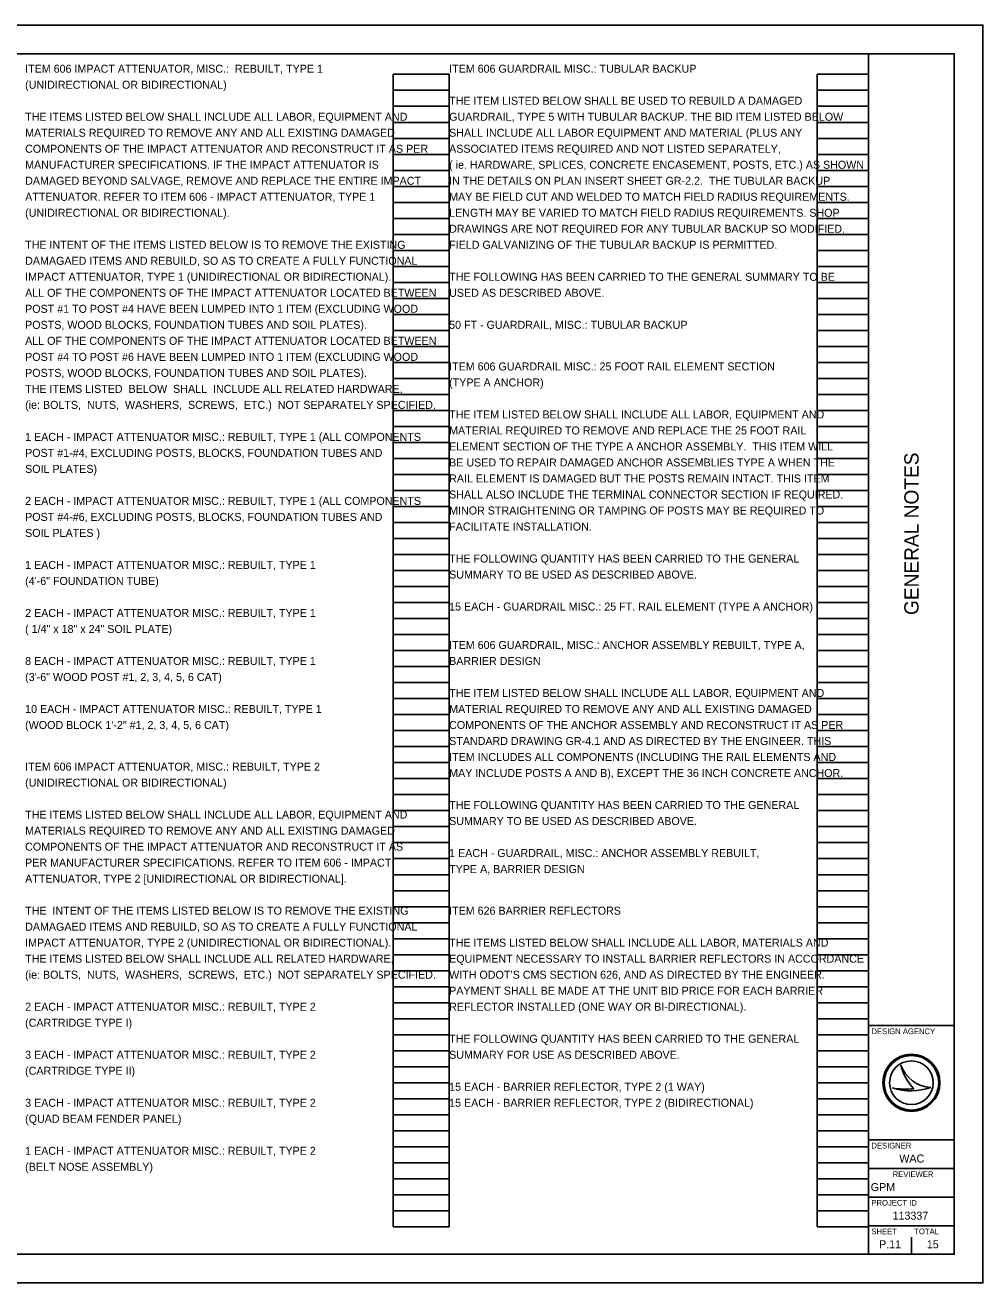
# Model space of a CAD drawing. Extents: x 0 to 34, y 0 to 22.
# Drawn here: x 17.24 to 34, y 0 to 22 of the extents above; entities that cross this region are included whole.
import ezdxf

# ---------------------------------------------------------------- set-up
doc = ezdxf.new("R2010")
doc.units = 0
for name, color, linetype in [('SH_Border', 7, 'Continuous'), ('SH_Cut_Line', 7, 'Continuous'), ('SH_Data', 7, 'Continuous'), ('SH_Text', 7, 'Continuous')]:
    doc.layers.add(name, color=color, linetype=linetype)

msp = doc.modelspace()

# ---------------------------------------------------------------- linework, layer by layer
at = {"layer": 'SH_Border'}
for p, q in [((32, 0.5), (32, 21.5)), ((32, 4.5), (33.5, 4.5)), ((32, 2.5), (33.5, 2.5)), ((32, 2), (33.5, 2)), ((32, 1.5), (33.5, 1.5)), ((32, 1), (33.5, 1))]:
    msp.add_line(p, q, dxfattribs=at)
msp.add_lwpolyline([(1.5, 21.5), (33.5, 21.5), (33.5, 0.5), (1.5, 0.5)], close=True, dxfattribs=at)
at = {"layer": 'SH_Cut_Line'}
msp.add_lwpolyline([(0, 0), (34, 0), (34, 22), (0, 22)], close=True, dxfattribs=at)
at = {"layer": 'SH_Data'}
for p, q in [((23.68, 0.98), (23.68, 21.14)), ((23.68, 21.14), (24.66, 21.14)), ((24.66, 0.98), (24.66, 21.14)), ((31.1, 0.98), (31.1, 21.14)), ((31.1, 21.14), (32, 21.14)), ((32, 0.98), (32, 21.14)), ((23.68, 20.86), (24.66, 20.86)), ((31.1, 20.86), (32, 20.86)), ((23.68, 20.58), (24.66, 20.58)), ((31.1, 20.58), (32, 20.58)), ((23.68, 20.3), (24.66, 20.3)), ((31.1, 20.3), (32, 20.3)), ((23.68, 20.02), (24.66, 20.02)), ((31.1, 20.02), (32, 20.02)), ((23.68, 19.74), (24.66, 19.74)), ((31.1, 19.74), (32, 19.74)), ((23.68, 19.46), (24.66, 19.46)), ((31.1, 19.46), (32, 19.46)), ((23.68, 19.18), (24.66, 19.18)), ((31.1, 19.18), (32, 19.18)), ((23.68, 18.9), (24.66, 18.9)), ((31.1, 18.9), (32, 18.9)), ((23.68, 18.62), (24.66, 18.62)), ((31.1, 18.62), (32, 18.62)), ((23.68, 18.34), (24.66, 18.34)), ((31.1, 18.34), (32, 18.34)), ((23.68, 18.06), (24.66, 18.06)), ((31.1, 18.06), (32, 18.06)), ((23.68, 17.78), (24.66, 17.78)), ((31.1, 17.78), (32, 17.78)), ((23.68, 17.5), (24.66, 17.5)), ((31.1, 17.5), (32, 17.5)), ((23.68, 17.22), (24.66, 17.22)), ((31.1, 17.22), (32, 17.22)), ((23.68, 16.94), (24.66, 16.94)), ((31.1, 16.94), (32, 16.94)), ((23.68, 16.66), (24.66, 16.66)), ((31.1, 16.66), (32, 16.66)), ((23.68, 16.38), (24.66, 16.38)), ((31.1, 16.38), (32, 16.38)), ((23.68, 16.1), (24.66, 16.1)), ((31.1, 16.1), (32, 16.1)), ((23.68, 15.82), (24.66, 15.82)), ((31.1, 15.82), (32, 15.82)), ((23.68, 15.54), (24.66, 15.54)), ((31.1, 15.54), (32, 15.54)), ((23.68, 15.26), (24.66, 15.26)), ((31.1, 15.26), (32, 15.26)), ((23.68, 14.98), (24.66, 14.98)), ((31.1, 14.98), (32, 14.98)), ((23.68, 14.7), (24.66, 14.7)), ((31.1, 14.7), (32, 14.7)), ((23.68, 14.42), (24.66, 14.42)), ((31.1, 14.42), (32, 14.42)), ((23.68, 14.14), (24.66, 14.14)), ((31.1, 14.14), (32, 14.14)), ((23.68, 13.86), (24.66, 13.86)), ((31.1, 13.86), (32, 13.86)), ((23.68, 13.58), (24.66, 13.58)), ((31.1, 13.58), (32, 13.58)), ((23.68, 13.3), (24.66, 13.3)), ((31.1, 13.3), (32, 13.3)), ((23.68, 13.02), (24.66, 13.02)), ((31.1, 13.02), (32, 13.02)), ((23.68, 12.74), (24.66, 12.74)), ((31.1, 12.74), (32, 12.74)), ((23.68, 12.46), (24.66, 12.46)), ((31.1, 12.46), (32, 12.46)), ((23.68, 12.18), (24.66, 12.18)), ((31.1, 12.18), (32, 12.18)), ((23.68, 11.9), (24.66, 11.9)), ((31.1, 11.9), (32, 11.9)), ((23.68, 11.62), (24.66, 11.62)), ((31.1, 11.62), (32, 11.62)), ((23.68, 11.34), (24.66, 11.34)), ((31.1, 11.34), (32, 11.34)), ((23.68, 11.06), (24.66, 11.06)), ((31.1, 11.06), (32, 11.06)), ((23.68, 10.78), (24.66, 10.78)), ((31.1, 10.78), (32, 10.78)), ((23.68, 10.5), (24.66, 10.5)), ((31.1, 10.5), (32, 10.5)), ((23.68, 10.22), (24.66, 10.22)), ((31.1, 10.22), (32, 10.22)), ((23.68, 9.94), (24.66, 9.94)), ((31.1, 9.94), (32, 9.94)), ((23.68, 9.66), (24.66, 9.66)), ((31.1, 9.66), (32, 9.66)), ((23.68, 9.38), (24.66, 9.38)), ((31.1, 9.38), (32, 9.38)), ((23.68, 9.1), (24.66, 9.1)), ((31.1, 9.1), (32, 9.1)), ((23.68, 8.82), (24.66, 8.82)), ((31.1, 8.82), (32, 8.82)), ((23.68, 8.54), (24.66, 8.54)), ((31.1, 8.54), (32, 8.54)), ((23.68, 8.26), (24.66, 8.26)), ((31.1, 8.26), (32, 8.26)), ((23.68, 7.98), (24.66, 7.98)), ((31.1, 7.98), (32, 7.98)), ((23.68, 7.7), (24.66, 7.7)), ((31.1, 7.7), (32, 7.7)), ((23.68, 7.42), (24.66, 7.42)), ((31.1, 7.42), (32, 7.42)), ((23.68, 7.14), (24.66, 7.14)), ((31.1, 7.14), (32, 7.14)), ((23.68, 6.86), (24.66, 6.86)), ((31.1, 6.86), (32, 6.86)), ((23.68, 6.58), (24.66, 6.58)), ((31.1, 6.58), (32, 6.58)), ((23.68, 6.3), (24.66, 6.3)), ((31.1, 6.3), (32, 6.3)), ((23.68, 6.02), (24.66, 6.02)), ((31.1, 6.02), (32, 6.02)), ((23.68, 5.74), (24.66, 5.74)), ((31.1, 5.74), (32, 5.74)), ((23.68, 5.46), (24.66, 5.46)), ((31.1, 5.46), (32, 5.46)), ((23.68, 5.18), (24.66, 5.18)), ((31.1, 5.18), (32, 5.18)), ((23.68, 4.9), (24.66, 4.9)), ((31.1, 4.9), (32, 4.9)), ((23.68, 4.62), (24.66, 4.62)), ((31.1, 4.62), (32, 4.62)), ((23.68, 4.34), (24.66, 4.34)), ((31.1, 4.34), (32, 4.34)), ((23.68, 4.06), (24.66, 4.06)), ((31.1, 4.06), (32, 4.06)), ((23.68, 3.78), (24.66, 3.78)), ((31.1, 3.78), (32, 3.78)), ((32.567, 3.81), (32.567, 3.81)), ((23.68, 3.5), (24.66, 3.5)), ((31.1, 3.5), (32, 3.5)), ((32.417, 3.41), (32.417, 3.41)), ((32.75, 3.5), (32.75, 3.5)), ((33.087, 3.419), (33.087, 3.419)), ((23.68, 3.22), (24.66, 3.22)), ((31.1, 3.22), (32, 3.22)), ((23.68, 2.94), (24.66, 2.94)), ((31.1, 2.94), (32, 2.94)), ((23.68, 2.66), (24.66, 2.66)), ((31.1, 2.66), (32, 2.66)), ((23.68, 2.38), (24.66, 2.38)), ((31.1, 2.38), (32, 2.38)), ((23.68, 2.1), (24.66, 2.1)), ((31.1, 2.1), (32, 2.1)), ((23.68, 1.82), (24.66, 1.82)), ((31.1, 1.82), (32, 1.82)), ((23.68, 1.54), (24.66, 1.54)), ((31.1, 1.54), (32, 1.54)), ((23.68, 1.26), (24.66, 1.26)), ((31.1, 1.26), (32, 1.26)), ((23.68, 0.98), (24.66, 0.98)), ((31.1, 0.98), (32, 0.98)), ((32.375, 0.675), (32.375, 0.675)), ((32.75, 0.5), (32.75, 0.8))]:
    msp.add_line(p, q, dxfattribs=at)
for radius in [0.5, 0.477, 0.477, 0.382]:
    msp.add_circle((32.75, 3.5), radius, dxfattribs=at)
for centre, radius, start, end in [((33.116, 3.998), 0.58, 198.9257, 198.9319), ((33.347, 3.97), 0.796, 191.6379, 191.6421), ((33.116, 3.998), 0.58, 198.9319, 267.1657), ((33.347, 3.97), 0.796, 191.6421, 226.0947), ((32.739, 4.37), 1.013, 251.4576, 290.0832), ((32.648, 4.654), 1.266, 259.4964, 259.4995), ((32.739, 4.37), 1.013, 251.4527, 251.4576), ((32.648, 4.654), 1.266, 259.4995, 276.6672)]:
    msp.add_arc(centre, radius, start, end, dxfattribs=at)

# ---------------------------------------------------------------- texts
msp.add_text('GENERAL NOTES', height=0.25, rotation=90, dxfattribs=at).set_placement((32.875, 11.682))
for s, height, p in [('DESIGN AGENCY', 0.1, (32.05, 4.35)), ('DESIGNER', 0.1, (32.05, 2.35)), ('WAC', 0.14, (32.538, 2.105)), ('REVIEWER', 0.1, (32.422, 1.85)), ('GPM', 0.14, (32.038, 1.605)), ('PROJECT ID', 0.1, (32.05, 1.35)), ('113337', 0.14, (32.42, 1.105)), ('SHEET', 0.1, (32.05, 0.85)), ('TOTAL', 0.1, (32.8, 0.85)), ('P.11', 0.14, (32.184, 0.605)), ('15', 0.14, (33.02, 0.605))]:
    msp.add_text(s, height=height, dxfattribs=at).set_placement(p)
at = {"layer": 'SH_Text'}
for s, p in [('ITEM 606 IMPACT ATTENUATOR, MISC.:  REBUILT, TYPE 1', (17.24, 21.168)), ('ITEM 606 GUARDRAIL MISC.: TUBULAR BACKUP', (24.66, 21.168)), ('(UNIDIRECTIONAL OR BIDIRECTIONAL)', (17.24, 20.888)), ('THE ITEM LISTED BELOW SHALL BE USED TO REBUILD A DAMAGED', (24.66, 20.608)), ('THE ITEMS LISTED BELOW SHALL INCLUDE ALL LABOR, EQUIPMENT AND', (17.24, 20.328)), ('GUARDRAIL, TYPE 5 WITH TUBULAR BACKUP. THE BID ITEM LISTED BELOW', (24.66, 20.328)), ('MATERIALS REQUIRED TO REMOVE ANY AND ALL EXISTING DAMAGED', (17.24, 20.048)), ('SHALL INCLUDE ALL LABOR EQUIPMENT AND MATERIAL (PLUS ANY', (24.66, 20.048)), ('COMPONENTS OF THE IMPACT ATTENUATOR AND RECONSTRUCT IT AS PER', (17.24, 19.768)), ('ASSOCIATED ITEMS REQUIRED AND NOT LISTED SEPARATELY,', (24.66, 19.768)), ('MANUFACTURER SPECIFICATIONS. IF THE IMPACT ATTENUATOR IS', (17.24, 19.488)), ('( ie. HARDWARE, SPLICES, CONCRETE ENCASEMENT, POSTS, ETC.) AS SHOWN', (24.66, 19.488)), ('DAMAGED BEYOND SALVAGE, REMOVE AND REPLACE THE ENTIRE IMPACT', (17.24, 19.208)), ('IN THE DETAILS ON PLAN INSERT SHEET GR-2.2.  THE TUBULAR BACKUP', (24.66, 19.208)), ('ATTENUATOR. REFER TO ITEM 606 - IMPACT ATTENUATOR, TYPE 1', (17.24, 18.928)), ('MAY BE FIELD CUT AND WELDED TO MATCH FIELD RADIUS REQUIREMENTS.', (24.66, 18.928)), ('(UNIDIRECTIONAL OR BIDIRECTIONAL).', (17.24, 18.648)), ('LENGTH MAY BE VARIED TO MATCH FIELD RADIUS REQUIREMENTS. SHOP', (24.66, 18.648)), ('DRAWINGS ARE NOT REQUIRED FOR ANY TUBULAR BACKUP SO MODIFIED.', (24.66, 18.368)), ('THE INTENT OF THE ITEMS LISTED BELOW IS TO REMOVE THE EXISTING', (17.24, 18.088)), ('FIELD GALVANIZING OF THE TUBULAR BACKUP IS PERMITTED. ', (24.66, 18.088)), ('DAMAGAED ITEMS AND REBUILD, SO AS TO CREATE A FULLY FUNCTIONAL', (17.24, 17.808)), ('IMPACT ATTENUATOR, TYPE 1 (UNIDIRECTIONAL OR BIDIRECTIONAL).', (17.24, 17.528)), ('THE FOLLOWING HAS BEEN CARRIED TO THE GENERAL SUMMARY TO BE', (24.66, 17.528)), ('ALL OF THE COMPONENTS OF THE IMPACT ATTENUATOR LOCATED BETWEEN', (17.24, 17.248)), ('USED AS DESCRIBED ABOVE.', (24.66, 17.248)), ('POST #1 TO POST #4 HAVE BEEN LUMPED INTO 1 ITEM (EXCLUDING WOOD', (17.24, 16.968)), ('POSTS, WOOD BLOCKS, FOUNDATION TUBES AND SOIL PLATES).', (17.24, 16.688)), ('50 FT - GUARDRAIL, MISC.: TUBULAR BACKUP ', (24.66, 16.688)), ('ALL OF THE COMPONENTS OF THE IMPACT ATTENUATOR LOCATED BETWEEN', (17.24, 16.408)), ('POST #4 TO POST #6 HAVE BEEN LUMPED INTO 1 ITEM (EXCLUDING WOOD', (17.24, 16.128)), ('ITEM 606 GUARDRAIL MISC.: 25 FOOT RAIL ELEMENT SECTION', (24.66, 15.96)), ('POSTS, WOOD BLOCKS, FOUNDATION TUBES AND SOIL PLATES).', (17.24, 15.848)), ('THE ITEMS LISTED  BELOW  SHALL  INCLUDE ALL RELATED HARDWARE,', (17.24, 15.568)), ('(TYPE A ANCHOR)', (24.66, 15.68)), ('(ie: BOLTS,  NUTS,  WASHERS,  SCREWS,  ETC.)  NOT SEPARATELY SPECIFIED.  ', (17.24, 15.288)), ('THE ITEM LISTED BELOW SHALL INCLUDE ALL LABOR, EQUIPMENT AND', (24.66, 15.12)), ('MATERIAL REQUIRED TO REMOVE AND REPLACE THE 25 FOOT RAIL', (24.66, 14.84)), ('1 EACH - IMPACT ATTENUATOR MISC.: REBUILT, TYPE 1 (ALL COMPONENTS', (17.24, 14.728)), ('POST #1-#4, EXCLUDING POSTS, BLOCKS, FOUNDATION TUBES AND', (17.24, 14.448)), ('ELEMENT SECTION OF THE TYPE A ANCHOR ASSEMBLY.  THIS ITEM WILL', (24.66, 14.56)), ('SOIL PLATES)', (17.24, 14.168)), ('BE USED TO REPAIR DAMAGED ANCHOR ASSEMBLIES TYPE A WHEN THE', (24.66, 14.28)), ('RAIL ELEMENT IS DAMAGED BUT THE POSTS REMAIN INTACT. THIS ITEM', (24.66, 14)), ('SHALL ALSO INCLUDE THE TERMINAL CONNECTOR SECTION IF REQUIRED.', (24.66, 13.72)), ('2 EACH - IMPACT ATTENUATOR MISC.: REBUILT, TYPE 1 (ALL COMPONENTS', (17.24, 13.608)), ('POST #4-#6, EXCLUDING POSTS, BLOCKS, FOUNDATION TUBES AND', (17.24, 13.328)), ('MINOR STRAIGHTENING OR TAMPING OF POSTS MAY BE REQUIRED TO', (24.66, 13.44)), ('FACILITATE INSTALLATION.  ', (24.66, 13.16)), ('SOIL PLATES )', (17.24, 13.048)), ('1 EACH - IMPACT ATTENUATOR MISC.: REBUILT, TYPE 1', (17.24, 12.488)), ('THE FOLLOWING QUANTITY HAS BEEN CARRIED TO THE GENERAL', (24.66, 12.6)), ('(4\'-6" FOUNDATION TUBE)', (17.24, 12.208)), ('SUMMARY TO BE USED AS DESCRIBED ABOVE.   ', (24.66, 12.32)), ('15 EACH - GUARDRAIL MISC.: 25 FT. RAIL ELEMENT (TYPE A ANCHOR) ', (24.66, 11.76)), ('2 EACH - IMPACT ATTENUATOR MISC.: REBUILT, TYPE 1', (17.24, 11.648)), ('( 1/4" x 18" x 24" SOIL PLATE)', (17.24, 11.368)), ('ITEM 606 GUARDRAIL, MISC.: ANCHOR ASSEMBLY REBUILT, TYPE A,', (24.66, 11.088)), ('8 EACH - IMPACT ATTENUATOR MISC.: REBUILT, TYPE 1', (17.24, 10.808)), ('BARRIER DESIGN', (24.66, 10.808)), ('(3\'-6" WOOD POST #1, 2, 3, 4, 5, 6 CAT)', (17.24, 10.528)), ('THE ITEM LISTED BELOW SHALL INCLUDE ALL LABOR, EQUIPMENT AND', (24.66, 10.248)), ('10 EACH - IMPACT ATTENUATOR MISC.: REBUILT, TYPE 1', (17.24, 9.968)), ('MATERIAL REQUIRED TO REMOVE ANY AND ALL EXISTING DAMAGED', (24.66, 9.968)), ('(WOOD BLOCK 1\'-2" #1, 2, 3, 4, 5, 6 CAT)', (17.24, 9.688)), ('COMPONENTS OF THE ANCHOR ASSEMBLY AND RECONSTRUCT IT AS PER', (24.66, 9.688)), ('STANDARD DRAWING GR-4.1 AND AS DIRECTED BY THE ENGINEER. THIS', (24.66, 9.408)), ('ITEM INCLUDES ALL COMPONENTS (INCLUDING THE RAIL ELEMENTS AND', (24.66, 9.128)), ('ITEM 606 IMPACT ATTENUATOR, MISC.: REBUILT, TYPE 2', (17.24, 8.96)), ('(UNIDIRECTIONAL OR BIDIRECTIONAL)', (17.24, 8.68)), ('MAY INCLUDE POSTS A AND B), EXCEPT THE 36 INCH CONCRETE ANCHOR.  ', (24.66, 8.848)), ('THE FOLLOWING QUANTITY HAS BEEN CARRIED TO THE GENERAL', (24.66, 8.288)), ('THE ITEMS LISTED BELOW SHALL INCLUDE ALL LABOR, EQUIPMENT AND', (17.24, 8.12)), ('SUMMARY TO BE USED AS DESCRIBED ABOVE.   ', (24.66, 8.008)), ('MATERIALS REQUIRED TO REMOVE ANY AND ALL EXISTING DAMAGED', (17.24, 7.84)), ('COMPONENTS OF THE IMPACT ATTENUATOR AND RECONSTRUCT IT AS', (17.24, 7.56)), ('1 EACH - GUARDRAIL, MISC.: ANCHOR ASSEMBLY REBUILT,', (24.66, 7.448)), ('PER MANUFACTURER SPECIFICATIONS. REFER TO ITEM 606 - IMPACT', (17.24, 7.28)), ('TYPE A, BARRIER DESIGN ', (24.66, 7.168)), ('ATTENUATOR, TYPE 2 [UNIDIRECTIONAL OR BIDIRECTIONAL].', (17.24, 7)), ('THE  INTENT OF THE ITEMS LISTED BELOW IS TO REMOVE THE EXISTING', (17.24, 6.44)), ('ITEM 626 BARRIER REFLECTORS', (24.66, 6.44)), ('DAMAGAED ITEMS AND REBUILD, SO AS TO CREATE A FULLY FUNCTIONAL', (17.24, 6.16)), ('IMPACT ATTENUATOR, TYPE 2 (UNIDIRECTIONAL OR BIDIRECTIONAL).', (17.24, 5.88)), ('THE ITEMS LISTED BELOW SHALL INCLUDE ALL LABOR, MATERIALS AND', (24.66, 5.88)), ('THE ITEMS LISTED BELOW SHALL INCLUDE ALL RELATED HARDWARE,', (17.24, 5.6)), ('EQUIPMENT NECESSARY TO INSTALL BARRIER REFLECTORS IN ACCORDANCE', (24.66, 5.6)), ('(ie: BOLTS,  NUTS,  WASHERS,  SCREWS,  ETC.)  NOT SEPARATELY SPECIFIED.', (17.24, 5.32)), ('WITH ODOT’S CMS SECTION 626, AND AS DIRECTED BY THE ENGINEER.', (24.66, 5.32)), ('PAYMENT SHALL BE MADE AT THE UNIT BID PRICE FOR EACH BARRIER', (24.66, 5.04)), ('2 EACH - IMPACT ATTENUATOR MISC.: REBUILT, TYPE 2 ', (17.24, 4.76)), ('REFLECTOR INSTALLED (ONE WAY OR BI-DIRECTIONAL).  ', (24.66, 4.76)), ('(CARTRIDGE TYPE I)', (17.24, 4.48)), ('THE FOLLOWING QUANTITY HAS BEEN CARRIED TO THE GENERAL', (24.66, 4.2)), ('3 EACH - IMPACT ATTENUATOR MISC.: REBUILT, TYPE 2', (17.24, 3.92)), ('SUMMARY FOR USE AS DESCRIBED ABOVE.  ', (24.66, 3.92)), ('(CARTRIDGE TYPE II)', (17.24, 3.64)), ('15 EACH - BARRIER REFLECTOR, TYPE 2 (1 WAY)', (24.66, 3.36)), ('3 EACH - IMPACT ATTENUATOR MISC.: REBUILT, TYPE 2', (17.24, 3.08)), ('15 EACH - BARRIER REFLECTOR, TYPE 2 (BIDIRECTIONAL)', (24.66, 3.08)), ('(QUAD BEAM FENDER PANEL)', (17.24, 2.8)), ('1 EACH - IMPACT ATTENUATOR MISC.: REBUILT, TYPE 2', (17.24, 2.24)), ('(BELT NOSE ASSEMBLY)', (17.24, 1.96))]:
    msp.add_text(s, height=0.14, dxfattribs=at).set_placement(p)

doc.saveas('drawing.dxf')
